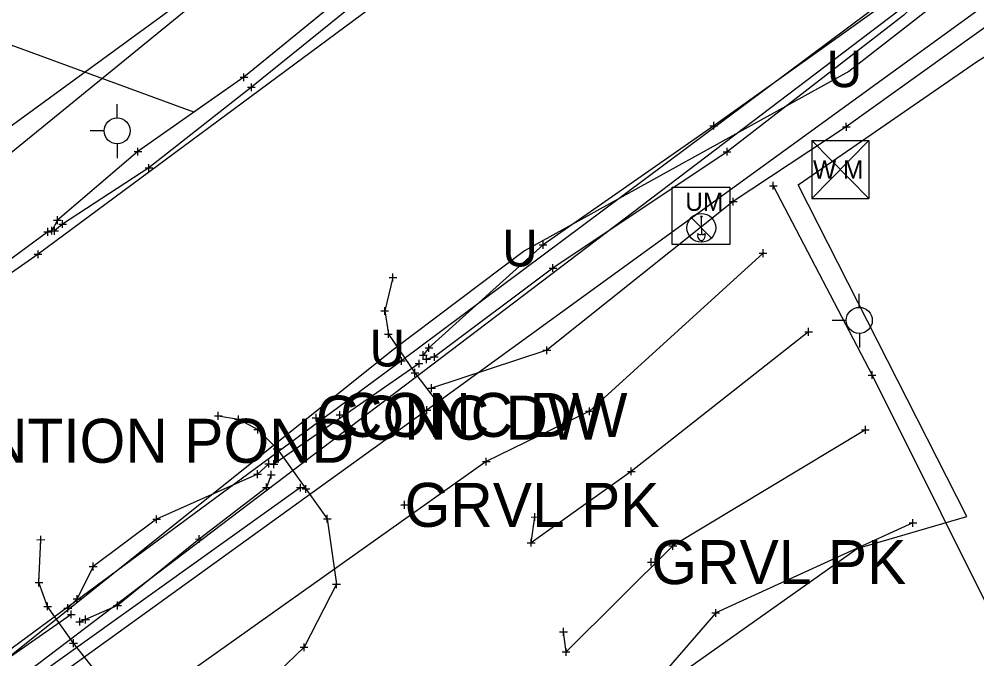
# Model space of a CAD drawing. Extents: x -1 to 1157254, y -1 to 2021979.
# Drawn here: x 1149976.9 to 1150133.6, y 2019339.4 to 2019444.1 of the extents above; entities that cross this region are included whole.
import ezdxf

# ---------------------------------------------------------------- set-up
doc = ezdxf.new("R2010")
doc.units = 0
for name, color, linetype in [('S_BUILDING_ANNOT', 7, 'Continuous'), ('S_CAL_CORNER', 7, 'Continuous'), ('S_CAL_CORNER_ANNOT', 7, 'Continuous'), ('S_CATCH_BASIN', 7, 'Continuous'), ('S_CONTOUR_ANNOT', 7, 'Continuous'), ('S_CONTOUR_MAJOR', 7, 'Continuous'), ('S_CTL_TABLE', 7, 'Continuous'), ('S_CURB', 7, 'Continuous'), ('S_DITCHLINE', 7, 'Continuous'), ('S_DRIVEWAY_ANNOT', 7, 'Continuous'), ('S_DROP_INLET', 7, 'Continuous'), ('S_DROP_INLET_ANNOT', 7, 'Continuous'), ('S_EDGE_BITUMINOUS_ANNOT', 7, 'Continuous'), ('S_ENV_CONSTRAINT', 7, 'Continuous'), ('S_FENCE', 7, 'Continuous'), ('S_GAS_PUMP_ISLAND_ANNOT', 7, 'Continuous'), ('S_GATE', 7, 'Continuous')]:
    doc.layers.add(name, color=color, linetype=linetype)

msp = doc.modelspace()

# ---------------------------------------------------------------- linework, layer by layer
at = {"layer": 'S_BUILDING_ANNOT'}
for p, q in [((1150013.04, 2019434.58), (1150014.31, 2019434.58)), ((1150013.68, 2019433.94), (1150013.68, 2019435.21)), ((1150013.68, 2019434.58), (1150013.68, 2019434.58)), ((1150014.26, 2019432.93), (1150015.53, 2019432.93)), ((1150014.9, 2019432.3), (1150014.9, 2019433.57)), ((1150014.9, 2019432.93), (1150014.9, 2019432.93)), ((1150089.93, 2019426.64), (1150091.2, 2019426.65)), ((1150090.57, 2019426.01), (1150090.56, 2019427.28)), ((1150090.57, 2019426.64), (1150090.57, 2019426.64)), ((1149995.68, 2019422.4), (1149996.95, 2019422.4)), ((1149996.31, 2019421.76), (1149996.31, 2019423.04)), ((1149996.31, 2019422.4), (1149996.31, 2019422.4)), ((1150092.11, 2019422.39), (1150093.38, 2019422.39)), ((1150092.74, 2019421.75), (1150092.74, 2019423.02)), ((1150092.74, 2019422.39), (1150092.74, 2019422.39)), ((1149998.13, 2019419.09), (1149998.13, 2019420.37)), ((1149997.5, 2019419.73), (1149998.77, 2019419.73)), ((1149998.13, 2019419.73), (1149998.13, 2019419.73)), ((1150100.32, 2019416.19), (1150100.32, 2019417.46)), ((1150099.68, 2019416.83), (1150100.96, 2019416.83)), ((1150100.32, 2019416.83), (1150100.32, 2019416.83)), ((1149982.5, 2019411.2), (1149983.77, 2019411.2)), ((1149983.14, 2019410.56), (1149983.13, 2019411.83)), ((1149983.14, 2019411.2), (1149983.14, 2019411.2)), ((1149984, 2019409.91), (1149983.99, 2019411.18)), ((1149980.94, 2019409.29), (1149982.21, 2019409.29)), ((1149981.58, 2019408.65), (1149981.58, 2019409.92)), ((1149981.58, 2019409.29), (1149981.58, 2019409.29)), ((1149981.59, 2019409.47), (1149982.86, 2019409.47)), ((1149982.05, 2019409.42), (1149983.32, 2019409.42)), ((1149982.23, 2019408.83), (1149982.23, 2019410.11)), ((1149982.23, 2019409.47), (1149982.23, 2019409.47)), ((1149982.69, 2019408.79), (1149982.69, 2019410.06)), ((1149982.69, 2019409.42), (1149982.69, 2019409.42)), ((1149983.36, 2019410.55), (1149984.63, 2019410.55)), ((1149983.99, 2019410.55), (1149983.99, 2019410.55)), ((1150062.64, 2019406.51), (1150062.64, 2019407.78)), ((1149979.99, 2019404.96), (1149979.98, 2019406.23)), ((1150062, 2019407.14), (1150063.27, 2019407.14)), ((1150062.64, 2019407.14), (1150062.64, 2019407.14)), ((1149979.35, 2019405.6), (1149980.62, 2019405.6)), ((1149979.98, 2019405.6), (1149979.98, 2019405.6)), ((1150063.62, 2019403.36), (1150064.89, 2019403.36)), ((1150064.25, 2019402.72), (1150064.25, 2019404)), ((1150064.25, 2019403.36), (1150064.25, 2019403.36)), ((1150037.43, 2019401.8), (1150038.7, 2019401.8)), ((1150038.06, 2019401.16), (1150038.06, 2019402.44)), ((1150038.06, 2019401.8), (1150038.06, 2019401.8)), ((1150036.73, 2019395.69), (1150036.72, 2019396.96)), ((1150036.09, 2019396.33), (1150037.36, 2019396.33)), ((1150036.73, 2019396.33), (1150036.73, 2019396.33)), ((1150036.68, 2019392.54), (1150037.95, 2019392.55)), ((1150037.32, 2019391.91), (1150037.31, 2019393.18)), ((1150037.31, 2019392.55), (1150037.31, 2019392.55)), ((1150043.95, 2019389.67), (1150043.95, 2019390.94)), ((1150042.39, 2019389.11), (1150043.67, 2019389.12)), ((1150043.03, 2019388.48), (1150043.03, 2019389.75)), ((1150043.03, 2019389.11), (1150043.03, 2019389.11)), ((1150043.31, 2019390.31), (1150044.58, 2019390.31)), ((1150043.56, 2019387.8), (1150043.56, 2019389.07)), ((1150043.95, 2019390.31), (1150043.95, 2019390.31)), ((1150044.84, 2019388.18), (1150044.84, 2019389.45)), ((1150038.81, 2019388.15), (1150040.08, 2019388.15)), ((1150039.45, 2019387.52), (1150039.45, 2019388.79)), ((1150039.45, 2019388.15), (1150039.45, 2019388.15)), ((1150041.7, 2019387.71), (1150042.97, 2019387.71)), ((1150042.34, 2019387.07), (1150042.33, 2019388.34)), ((1150042.34, 2019387.71), (1150042.34, 2019387.71)), ((1150042.92, 2019388.43), (1150044.19, 2019388.43)), ((1150043.56, 2019388.43), (1150043.56, 2019388.43)), ((1150044.2, 2019388.81), (1150045.47, 2019388.82)), ((1150044.84, 2019388.82), (1150044.84, 2019388.82)), ((1150041.02, 2019386.2), (1150042.29, 2019386.21)), ((1150041.66, 2019385.57), (1150041.65, 2019386.84)), ((1150041.66, 2019386.2), (1150041.66, 2019386.2)), ((1150115.85, 2019385.84), (1150117.12, 2019385.84)), ((1150116.49, 2019385.2), (1150116.49, 2019386.47)), ((1150116.49, 2019385.84), (1150116.49, 2019385.84)), ((1150009.47, 2019378.53), (1150009.47, 2019379.8)), ((1150025.47, 2019378.23), (1150025.47, 2019379.51)), ((1150029.39, 2019378.68), (1150029.39, 2019379.95)), ((1150042.99, 2019380.11), (1150044.26, 2019380.11)), ((1150043.62, 2019379.47), (1150043.62, 2019380.74)), ((1150043.62, 2019380.11), (1150043.62, 2019380.11)), ((1150008.83, 2019379.16), (1150010.11, 2019379.16)), ((1150009.47, 2019379.16), (1150009.47, 2019379.16)), ((1150012.15, 2019378.61), (1150013.42, 2019378.61)), ((1150012.79, 2019377.97), (1150012.79, 2019379.24)), ((1150012.79, 2019378.61), (1150012.79, 2019378.61)), ((1150024.83, 2019378.87), (1150026.1, 2019378.87)), ((1150025.47, 2019378.87), (1150025.47, 2019378.87)), ((1150028.75, 2019379.32), (1150030.02, 2019379.32)), ((1150029.39, 2019379.32), (1150029.39, 2019379.32)), ((1150048.27, 2019376.92), (1150048.26, 2019378.19)), ((1150015.29, 2019376.92), (1150016.56, 2019376.92)), ((1150015.93, 2019376.28), (1150015.93, 2019377.55)), ((1150015.93, 2019376.92), (1150015.93, 2019376.92)), ((1150047.63, 2019377.55), (1150048.9, 2019377.55)), ((1150048.26, 2019377.55), (1150048.26, 2019377.55)), ((1150018.48, 2019373.76), (1150019.75, 2019373.76)), ((1150019.12, 2019373.13), (1150019.11, 2019374.4)), ((1150019.11, 2019373.76), (1150019.11, 2019373.76)), ((1150017.76, 2019370.69), (1150017.75, 2019371.96)), ((1150018.57, 2019370.63), (1150018.57, 2019371.9)), ((1150015.91, 2019368.99), (1150015.91, 2019370.26)), ((1150017.12, 2019371.32), (1150018.39, 2019371.33)), ((1150017.76, 2019371.33), (1150017.76, 2019371.33)), ((1150017.94, 2019371.26), (1150019.21, 2019371.26)), ((1150018.15, 2019368.9), (1150018.15, 2019370.18)), ((1150018.57, 2019371.26), (1150018.57, 2019371.26)), ((1150015.28, 2019369.62), (1150016.55, 2019369.63)), ((1150015.91, 2019369.62), (1150015.91, 2019369.62)), ((1150017.52, 2019369.54), (1150018.79, 2019369.54)), ((1150018.15, 2019369.54), (1150018.15, 2019369.54)), ((1150016.72, 2019367.47), (1150017.99, 2019367.47)), ((1150017.36, 2019366.83), (1150017.36, 2019368.11)), ((1150017.36, 2019367.47), (1150017.36, 2019367.47)), ((1150023.18, 2019367.21), (1150024.46, 2019367.22)), ((1150023.82, 2019366.58), (1150023.82, 2019367.85)), ((1150023.82, 2019367.21), (1150023.82, 2019367.21)), ((1150039.33, 2019364.6), (1150040.6, 2019364.6)), ((1150039.97, 2019363.96), (1150039.96, 2019365.24)), ((1150039.96, 2019364.6), (1150039.96, 2019364.6)), ((1149998.74, 2019362.24), (1150000.01, 2019362.24)), ((1149999.38, 2019361.6), (1149999.37, 2019362.88)), ((1149999.38, 2019362.24), (1149999.38, 2019362.24)), ((1150026.69, 2019362.33), (1150027.96, 2019362.33)), ((1150027.32, 2019361.7), (1150027.32, 2019362.97)), ((1150027.32, 2019362.33), (1150027.32, 2019362.33)), ((1149980.42, 2019358.27), (1149980.42, 2019359.54)), ((1150006.37, 2019358.38), (1150006.37, 2019359.65)), ((1149979.78, 2019358.9), (1149981.06, 2019358.91)), ((1149980.42, 2019358.91), (1149980.42, 2019358.91)), ((1150005.73, 2019359.01), (1150007, 2019359.02)), ((1150006.37, 2019359.01), (1150006.37, 2019359.01)), ((1149988.36, 2019354.52), (1149989.63, 2019354.53)), ((1149989, 2019353.89), (1149988.99, 2019355.16)), ((1149989, 2019354.53), (1149989, 2019354.53)), ((1150079.71, 2019355.22), (1150080.99, 2019355.23)), ((1150080.35, 2019354.59), (1150080.35, 2019355.86)), ((1150080.35, 2019355.23), (1150080.35, 2019355.23)), ((1149979.48, 2019351.89), (1149980.75, 2019351.89)), ((1149980.11, 2019351.26), (1149980.11, 2019352.53)), ((1149980.11, 2019351.89), (1149980.11, 2019351.89)), ((1150028.19, 2019351.61), (1150029.46, 2019351.61)), ((1150028.83, 2019350.97), (1150028.82, 2019352.24)), ((1150028.82, 2019351.61), (1150028.82, 2019351.61)), ((1149986.35, 2019348.58), (1149986.35, 2019349.85)), ((1149981.54, 2019347.35), (1149981.54, 2019348.62)), ((1149984.85, 2019347.06), (1149984.85, 2019348.33)), ((1149985.72, 2019349.21), (1149986.99, 2019349.21)), ((1149986.35, 2019349.21), (1149986.35, 2019349.21)), ((1149992.35, 2019348.14), (1149993.62, 2019348.14)), ((1149992.99, 2019347.5), (1149992.99, 2019348.77)), ((1149992.99, 2019348.14), (1149992.99, 2019348.14)), ((1149980.9, 2019347.99), (1149982.18, 2019347.99)), ((1149981.54, 2019347.99), (1149981.54, 2019347.99)), ((1149984.22, 2019347.69), (1149985.49, 2019347.69)), ((1149984.78, 2019346.68), (1149986.05, 2019346.68)), ((1149984.85, 2019347.69), (1149984.85, 2019347.69)), ((1149985.42, 2019346.04), (1149985.41, 2019347.32)), ((1149985.42, 2019346.68), (1149985.42, 2019346.68)), ((1149986.16, 2019345.48), (1149987.44, 2019345.48)), ((1149986.8, 2019344.84), (1149986.8, 2019346.12)), ((1149986.8, 2019345.48), (1149986.8, 2019345.48)), ((1149987.1, 2019345.84), (1149988.38, 2019345.84)), ((1149987.74, 2019345.21), (1149987.74, 2019346.48)), ((1149987.74, 2019345.84), (1149987.74, 2019345.84)), ((1149985.14, 2019341.96), (1149986.42, 2019341.97)), ((1149985.78, 2019341.33), (1149985.78, 2019342.6)), ((1149985.78, 2019341.96), (1149985.78, 2019341.96)), ((1150023.51, 2019340.67), (1150023.51, 2019341.94)), ((1150022.88, 2019341.3), (1150024.15, 2019341.31)), ((1150023.51, 2019341.31), (1150023.51, 2019341.31))]:
    msp.add_line(p, q, dxfattribs=at)
at = {"layer": 'S_CAL_CORNER'}
for p, q in [((1150086.87, 2019411.6), (1150090.2, 2019408.26)), ((1150088.38, 2019411.82), (1150088.69, 2019411.82)), ((1150088.54, 2019409.93), (1150088.54, 2019411.66)), ((1150088.54, 2019409.93), (1150088.54, 2019408.87)), ((1150087.94, 2019409.03), (1150087.94, 2019408.84)), ((1150089.13, 2019409.03), (1150089.14, 2019408.8))]:
    msp.add_line(p, q, dxfattribs=at)
msp.add_lwpolyline([(1150083.77, 2019416.59), (1150093.18, 2019416.59), (1150093.18, 2019407.18), (1150083.77, 2019407.18)], close=True, dxfattribs=at)
msp.add_circle((1150088.54, 2019409.93), 2.36, dxfattribs=at)
for centre, radius, start, end in [((1150088.54, 2019411.82), 0.156, 180, 0), ((1150088.36, 2019409.42), 0.58, 223.1344, 287.472), ((1150088.71, 2019409.43), 0.58, 252.528, 316.8656)]:
    msp.add_arc(centre, radius, start, end, dxfattribs=at)
msp.add_ellipse((1150088.54, 2019408.68), major_axis=(0, -0.82), ratio=0.744362, start_param=4.519801, end_param=8.000179, dxfattribs=at)
at = {"layer": 'S_CAL_CORNER_ANNOT'}
msp.add_lwpolyline([(1150682.05, 2019865.85), (1150601.54, 2019813.47), (1150510.58, 2019743.97), (1150405.28, 2019665.92), (1150310.69, 2019593.56), (1150188.92, 2019499.64), (1150039.45, 2019388.15), (1149962.15, 2019331.17), (1149944.63, 2019319.08), (1149774.15, 2019191.52), (1149712.73, 2019145.6), (1149665.81, 2019108.74), (1149605.46, 2019057.66), (1149527.46, 2018983.58), (1149450.12, 2018902.93), (1149278.32, 2018738.82), (1149257.2, 2018716.38), (1149237.23, 2018691.25), (1149165.09, 2018617.77), (1149125.26, 2018579.57), (1149069.5, 2018523.84), (1149012.03, 2018473.77), (1148938.88, 2018408.55)], dxfattribs=at)
at = {"layer": 'S_CATCH_BASIN'}
for p, q in [((1149992.91, 2019427.91), (1149992.91, 2019430.16)), ((1149990.82, 2019425.78), (1149988.5, 2019425.78)), ((1149992.99, 2019421.36), (1149992.99, 2019423.69)), ((1150114.39, 2019396.9), (1150114.39, 2019399.15)), ((1150112.3, 2019394.77), (1150109.97, 2019394.77)), ((1150114.47, 2019390.35), (1150114.47, 2019392.68))]:
    msp.add_line(p, q, dxfattribs=at)
for centre in [(1149992.92, 2019425.8), (1150114.39, 2019394.79)]:
    msp.add_circle(centre, 2.13, dxfattribs=at)
at = {"layer": 'S_CONTOUR_ANNOT'}
for p, q in [((1150106.61, 2019424.2), (1150115.95, 2019424.2)), ((1150106.61, 2019424.2), (1150106.61, 2019414.71)), ((1150106.61, 2019424.2), (1150115.95, 2019414.71)), ((1150115.95, 2019424.2), (1150106.61, 2019414.71)), ((1150115.95, 2019424.2), (1150115.95, 2019414.71)), ((1150106.61, 2019414.71), (1150115.95, 2019414.71))]:
    msp.add_line(p, q, dxfattribs=at)
for points in [[(1150857.08, 2020031.73), (1150832.22, 2020016.43), (1150747.37, 2019963.08), (1150692.94, 2019929.63), (1150639.49, 2019893), (1150583.9, 2019856.96), (1150484.25, 2019790.85), (1150433.08, 2019750.74), (1150355.8, 2019695.65), (1150341.28, 2019681.73), (1150287.94, 2019641.18), (1150216.41, 2019587.25), (1150034.4, 2019445.88), (1149979.98, 2019405.6), (1149934.92, 2019374.11), (1149784.56, 2019258.12)], [(1150776.08, 2020000.06), (1150711.77, 2019956.26), (1150627.27, 2019900.66), (1150578.77, 2019864.96), (1150479.12, 2019798.68), (1150423.47, 2019764.16), (1150358.5, 2019722.73), (1150313.96, 2019690.01), (1150273.95, 2019661.03), (1150225.64, 2019623.26), (1150033.5, 2019468.9), (1149971.69, 2019423.78), (1149931.59, 2019393.98), (1149688.42, 2019230.92)]]:
    msp.add_lwpolyline(points, dxfattribs=at)
at = {"layer": 'S_CTL_TABLE'}
for p, q in [((1150111.64, 2019426.45), (1150112.91, 2019426.45)), ((1150112.28, 2019425.81), (1150112.27, 2019427.09)), ((1150112.27, 2019426.45), (1150112.27, 2019426.45)), ((1150093.1, 2019414.23), (1150094.38, 2019414.23)), ((1150093.74, 2019413.6), (1150093.74, 2019414.87)), ((1150093.74, 2019414.23), (1150093.74, 2019414.23)), ((1150098.65, 2019405.15), (1150098.65, 2019406.42)), ((1150098.01, 2019405.78), (1150099.28, 2019405.79)), ((1150098.65, 2019405.78), (1150098.65, 2019405.78)), ((1150106.09, 2019392.27), (1150106.09, 2019393.55)), ((1150105.46, 2019392.91), (1150106.73, 2019392.91)), ((1150106.09, 2019392.91), (1150106.09, 2019392.91)), ((1150063.25, 2019389.25), (1150063.25, 2019390.53)), ((1150062.62, 2019389.89), (1150063.89, 2019389.89)), ((1150063.25, 2019389.89), (1150063.25, 2019389.89)), ((1150044.38, 2019383.06), (1150044.38, 2019384.33)), ((1150043.75, 2019383.7), (1150045.02, 2019383.7)), ((1150044.38, 2019383.7), (1150044.38, 2019383.7)), ((1150069.57, 2019379.92), (1150070.84, 2019379.92)), ((1150070.21, 2019379.28), (1150070.21, 2019380.55)), ((1150070.21, 2019379.92), (1150070.21, 2019379.92)), ((1150114.75, 2019376.87), (1150116.03, 2019376.88)), ((1150115.39, 2019376.24), (1150115.39, 2019377.51)), ((1150115.39, 2019376.88), (1150115.39, 2019376.88)), ((1150052.7, 2019371.68), (1150053.97, 2019371.69)), ((1150053.34, 2019371.05), (1150053.33, 2019372.32)), ((1150053.34, 2019371.69), (1150053.34, 2019371.69)), ((1150076.43, 2019370.08), (1150077.7, 2019370.09)), ((1150077.07, 2019369.45), (1150077.07, 2019370.72)), ((1150077.07, 2019370.09), (1150077.07, 2019370.09)), ((1150022.3, 2019367.42), (1150023.57, 2019367.42)), ((1150022.94, 2019366.79), (1150022.94, 2019368.06)), ((1150022.94, 2019367.42), (1150022.94, 2019367.42)), ((1150060.66, 2019362.61), (1150061.94, 2019362.62)), ((1150061.3, 2019361.98), (1150061.3, 2019363.25)), ((1150061.3, 2019362.62), (1150061.3, 2019362.62)), ((1150123.17, 2019361.01), (1150123.16, 2019362.28)), ((1150122.53, 2019361.64), (1150123.8, 2019361.65)), ((1150123.16, 2019361.65), (1150123.16, 2019361.65)), ((1150060.69, 2019357.77), (1150060.69, 2019359.04)), ((1150060.05, 2019358.41), (1150061.33, 2019358.41)), ((1150060.69, 2019358.41), (1150060.69, 2019358.41)), ((1150083.24, 2019357.88), (1150084.52, 2019357.88)), ((1150083.88, 2019357.24), (1150083.88, 2019358.52)), ((1150083.88, 2019357.88), (1150083.88, 2019357.88)), ((1150090.26, 2019346.92), (1150091.53, 2019346.92)), ((1150090.9, 2019346.28), (1150090.89, 2019347.56)), ((1150090.9, 2019346.92), (1150090.9, 2019346.92)), ((1150065.33, 2019343.82), (1150066.61, 2019343.82)), ((1150065.97, 2019343.19), (1150065.97, 2019344.46)), ((1150065.97, 2019343.82), (1150065.97, 2019343.82)), ((1150065.77, 2019340.54), (1150067.04, 2019340.55)), ((1150066.41, 2019339.91), (1150066.41, 2019341.18)), ((1150066.41, 2019340.55), (1150066.41, 2019340.55))]:
    msp.add_line(p, q, dxfattribs=at)
at = {"layer": 'S_CURB'}
msp.add_lwpolyline([(1150100.32, 2019416.83), (1150116.49, 2019385.84), (1150139, 2019340.78)], dxfattribs=at)
at = {"layer": 'S_DITCHLINE'}
msp.add_lwpolyline([(1150340.68, 2019612.36), (1149611.97, 2019059.3)], dxfattribs=at)
at = {"layer": 'S_DRIVEWAY_ANNOT'}
for points in [[(1150056.81, 2019466.75), (1150055.2, 2019465.82), (1150042.75, 2019458.34), (1150013.68, 2019434.58), (1149996.31, 2019422.4), (1149983.14, 2019411.2), (1149982.23, 2019409.47)], [(1150057.12, 2019466.26), (1150056.18, 2019464.92), (1150043.98, 2019456.45), (1150014.9, 2019432.93), (1149998.13, 2019419.73), (1149983.99, 2019410.55), (1149982.69, 2019409.42)], [(1150130.08, 2019454.02), (1150128.61, 2019453.27), (1150119.66, 2019447.4), (1150090.57, 2019426.64), (1150062.64, 2019407.14), (1150043.95, 2019390.31), (1150043.03, 2019389.11)], [(1150130.24, 2019452.92), (1150129.46, 2019452.28), (1150121.67, 2019444.72), (1150092.74, 2019422.39), (1150064.25, 2019403.36), (1150044.84, 2019388.82), (1150043.56, 2019388.43)], [(1150017.76, 2019371.33), (1150015.91, 2019369.62), (1149999.38, 2019362.24), (1149989, 2019354.53), (1149986.35, 2019349.21), (1149984.85, 2019347.69)], [(1150018.15, 2019369.54), (1150017.36, 2019367.47), (1150006.37, 2019359.01), (1149992.99, 2019348.14), (1149987.74, 2019345.84), (1149986.8, 2019345.48)]]:
    msp.add_lwpolyline(points, dxfattribs=at)
at = {"layer": 'S_DROP_INLET'}
for points in [[(1150852.18, 2019973.05), (1150778.54, 2019928.45), (1150770.16, 2019919.18), (1150703.8, 2019877.29), (1150608.63, 2019809.12), (1150513.43, 2019739.89), (1150405.92, 2019663.65), (1150352.2, 2019622.72), (1150343.81, 2019614.74), (1150336.72, 2019606.98), (1150314.89, 2019591.84), (1150193.25, 2019498.28), (1150112.69, 2019435.49), (1150059.59, 2019406.16), (1150037.88, 2019389.79), (1149962.99, 2019329.91), (1149914.05, 2019297.4), (1149863.26, 2019256.98)], [(1150343.79, 2019722.31), (1149825.67, 2019300.1)]]:
    msp.add_lwpolyline(points, dxfattribs=at)
at = {"layer": 'S_DROP_INLET_ANNOT'}
for points in [[(1149981.58, 2019409.29), (1149929.91, 2019371.2)], [(1150042.34, 2019387.71), (1150018.57, 2019371.26)], [(1149985.42, 2019346.68), (1149961.19, 2019329.83)]]:
    msp.add_lwpolyline(points, dxfattribs=at)
at = {"layer": 'S_EDGE_BITUMINOUS_ANNOT'}
for points in [[(1150136.86, 2019444.07), (1150112.27, 2019426.45), (1150093.74, 2019414.23), (1150063.25, 2019389.89), (1150044.38, 2019383.7)], [(1150098.65, 2019405.78), (1150070.21, 2019379.92), (1150053.34, 2019371.69), (1149964.9, 2019308.97), (1149935.2, 2019276.12), (1149902.7, 2019268.85), (1149887.31, 2019241.19), (1149873.58, 2019235.03), (1149841.75, 2019203.99), (1149814.28, 2019189.26), (1149796.69, 2019164.58), (1149760.44, 2019150.27), (1149732.83, 2019106.51), (1149696.46, 2019090.63), (1149668.72, 2019049.28), (1149655.8, 2019034.53)], [(1150106.09, 2019392.91), (1150077.07, 2019370.09), (1150060.69, 2019358.41), (1150061.3, 2019362.62)], [(1150115.39, 2019376.88), (1150083.88, 2019357.88), (1150066.41, 2019340.55), (1150065.97, 2019343.82)], [(1150022.94, 2019367.42), (1149964.57, 2019325.71), (1149928.47, 2019292.59), (1149899.27, 2019281.43), (1149874.7, 2019256.95), (1149856.33, 2019243.33), (1149830.41, 2019224.78), (1149802.41, 2019203), (1149780.2, 2019183.24), (1149750.6, 2019162.52), (1149713.11, 2019125.27), (1149684.98, 2019104.2), (1149645.14, 2019067.71), (1149630.42, 2019055.47)], [(1150123.16, 2019361.65), (1150090.9, 2019346.92), (1150071.9, 2019325.03), (1150065.44, 2019318.94)]]:
    msp.add_lwpolyline(points, dxfattribs=at)
at = {"layer": 'S_ENV_CONSTRAINT'}
for points in [[(1150038.06, 2019401.8), (1150036.73, 2019396.33), (1150037.31, 2019392.55), (1150041.66, 2019386.2), (1150048.26, 2019377.55)], [(1150009.47, 2019379.16), (1150012.79, 2019378.61), (1150015.93, 2019376.92), (1150019.11, 2019373.76), (1150023.82, 2019367.21), (1150027.32, 2019362.33), (1150028.82, 2019351.61), (1150023.51, 2019341.31), (1150016.42, 2019334.48), (1150006.77, 2019332.48), (1149996.51, 2019333.44), (1149991.36, 2019334.96), (1149985.78, 2019341.96), (1149981.54, 2019347.99), (1149980.11, 2019351.89), (1149980.42, 2019358.91)]]:
    msp.add_lwpolyline(points, dxfattribs=at)
at = {"layer": 'S_FENCE'}
msp.add_lwpolyline([(1150775.16, 2019913.88), (1150697.15, 2019862.05), (1150611.54, 2019805.47), (1150516.86, 2019735.37), (1150402.98, 2019659.79), (1150352.98, 2019622.15), (1150350.25, 2019606.72), (1150331.34, 2019598.55), (1150196.24, 2019490.87), (1150043.62, 2019380.11), (1149966.77, 2019324.72), (1149934.21, 2019308.48), (1149916.33, 2019289.12), (1149866.68, 2019250.91)], dxfattribs=at)
at = {"layer": 'S_GAS_PUMP_ISLAND_ANNOT'}
for points in [[(1150077.79, 2019331.81), (1150114.07, 2019357.49), (1150131.97, 2019362.71), (1150104.4, 2019416.99), (1150133.73, 2019437.2), (1150135.76, 2019438.46), (1150166.69, 2019459.53), (1150170.45, 2019462.06), (1150210.87, 2019456.7), (1150218.58, 2019436.94), (1150234.9, 2019452.62)], [(1150027.26, 2019445.68), (1150019.52, 2019439.35), (1150013.68, 2019434.58), (1150005.49, 2019428.84), (1149959.77, 2019445.61)]]:
    msp.add_lwpolyline(points, dxfattribs=at)

# ---------------------------------------------------------------- texts
at = {"layer": 'S_CAL_CORNER'}
msp.add_text('UM', height=2.999, dxfattribs=at).set_placement((1150085.91, 2019412.71))
at = {"layer": 'S_CONTOUR_ANNOT'}
msp.add_text('W M', height=2.999, dxfattribs=at).set_placement((1150106.82, 2019417.97))
at = {"layer": 'S_CONTOUR_MAJOR'}
for p in [(1150109.06, 2019432.95), (1150055.96, 2019403.62), (1150034.25, 2019387.25)]:
    msp.add_text('U', height=6, dxfattribs=at).set_placement(p)
at = {"layer": 'S_GATE'}
for s, p in [('CONC DW', (1150025.47, 2019375.27)), ('CONC DW', (1150029.39, 2019375.72)), ('LEVY FOR DENTENTION POND', (1149888.34, 2019371.49)), ('GRVL PK', (1150039.96, 2019361)), ('GRVL PK', (1150080.35, 2019351.63))]:
    msp.add_text(s, height=7.2, dxfattribs=at).set_placement(p)

doc.saveas('drawing.dxf')
